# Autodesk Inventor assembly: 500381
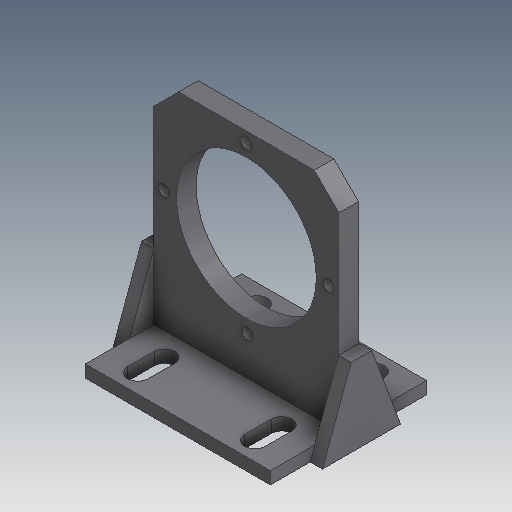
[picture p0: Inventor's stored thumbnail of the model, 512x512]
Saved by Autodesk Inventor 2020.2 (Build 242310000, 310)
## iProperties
Created: 1999-12
Part Number: 500381
Description: WMT-CP,FH,XX,MOUNT,GEARBOX
Document SubType Name: Assembly
Designer: sspink
Mass: 780.219 g
Surface Area: 378.111 cm^2
Volume: 99.2645 cm^3
Density: 7.86 g/cm^3
Control State: 0
Checked Out: False
Master: False
Shininess: 0.0
Length Units: 11269
Angle Units: 11279
Time Units: 11290
Mass Units: 11283
Length Display Precision: 3
Angle Display Precision: 2
Compacted: True
Dimensions: 110x76x102 mm
Mass: 0,78 kg
DocNumber: 500381.iam
Folder: 01 - Themengebiete\Simplification\01 - Packaging machine\
VDS_Category: 3D Komponenten
Density: 0.0
Volumn: 0.0
Area: 0.0
PropertySet Name: Model Information
Author: sspink
Revision Number: -
Title: WMT-CP,FH,XX,MOUNT,GEARBOX
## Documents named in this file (4)
- D:\07 - DEMODATEN\OTX 2019 - Dataset - UPDATE - Dez2019\Designs\07-Packing machine\500381.iam
- D:\07 - DEMODATEN\OTX 2019 - Dataset - UPDATE - Dez2019\Designs\07-Packing machine\Parts\ADSK-011365.ipt
- D:\07 - DEMODATEN\OTX 2019 - Dataset - UPDATE - Dez2019\Designs\07-Packing machine\Parts\ADSK-011366.ipt
- D:\07 - DEMODATEN\OTX 2019 - Dataset - UPDATE - Dez2019\Designs\07-Packing machine\Parts\ADSK-011367.ipt
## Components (4 placed, 3 different names)
1. ADSK-011366:1 — Flush:8, Flush:1, Flush:2, Flush:3, Flush:4, Flush:6, Flush:7, Mate:3
2. ADSK-011365:1 — Flush:8, Flush:1, Flush:2, Flush:9, Mate:1, Mate:2
3. ADSK-011367:1 — Flush:9, Flush:3, Mate:1, Flush:5
4. ADSK-011367:2 — Mate:2, Flush:4, Flush:5
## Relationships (12: Flush 9, Mate 3)
- Flush:8: ADSK-011366:1 ↔ ADSK-011365:1
- Flush:1: ADSK-011366:1 ↔ ADSK-011365:1
- Flush:2: ADSK-011366:1 ↔ ADSK-011365:1
- Flush:9: ADSK-011365:1 ↔ ADSK-011367:1
- Flush:3: ADSK-011366:1 ↔ ADSK-011367:1
- Mate:1: ADSK-011365:1 ↔ ADSK-011367:1
- Mate:2: ADSK-011365:1 ↔ ADSK-011367:2
- Flush:4: ADSK-011366:1 ↔ ADSK-011367:2
- Flush:5: ADSK-011367:1 ↔ ADSK-011367:2
- Flush:6: ADSK-011366:1
- Flush:7: ADSK-011366:1
- Mate:3: ADSK-011366:1
